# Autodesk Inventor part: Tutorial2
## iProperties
Shininess: 64.0
Length Units: 11269
Angle Units: 11279
Time Units: 11290
Mass Units: 11283
Length Display Precision: 3
Angle Display Precision: 2
Compacted: True
Part Number: Tutorial2
Document SubType Name: Modeling
Created: 2002-12
Designer: deepak
Density: 1 g/cm^3
Density: 0.0
Volumn: 0.0
Area: 0.0
PropertySet Name: Model Information
Control State: 0
Master: False
Checked Out: False
Author: deepak
